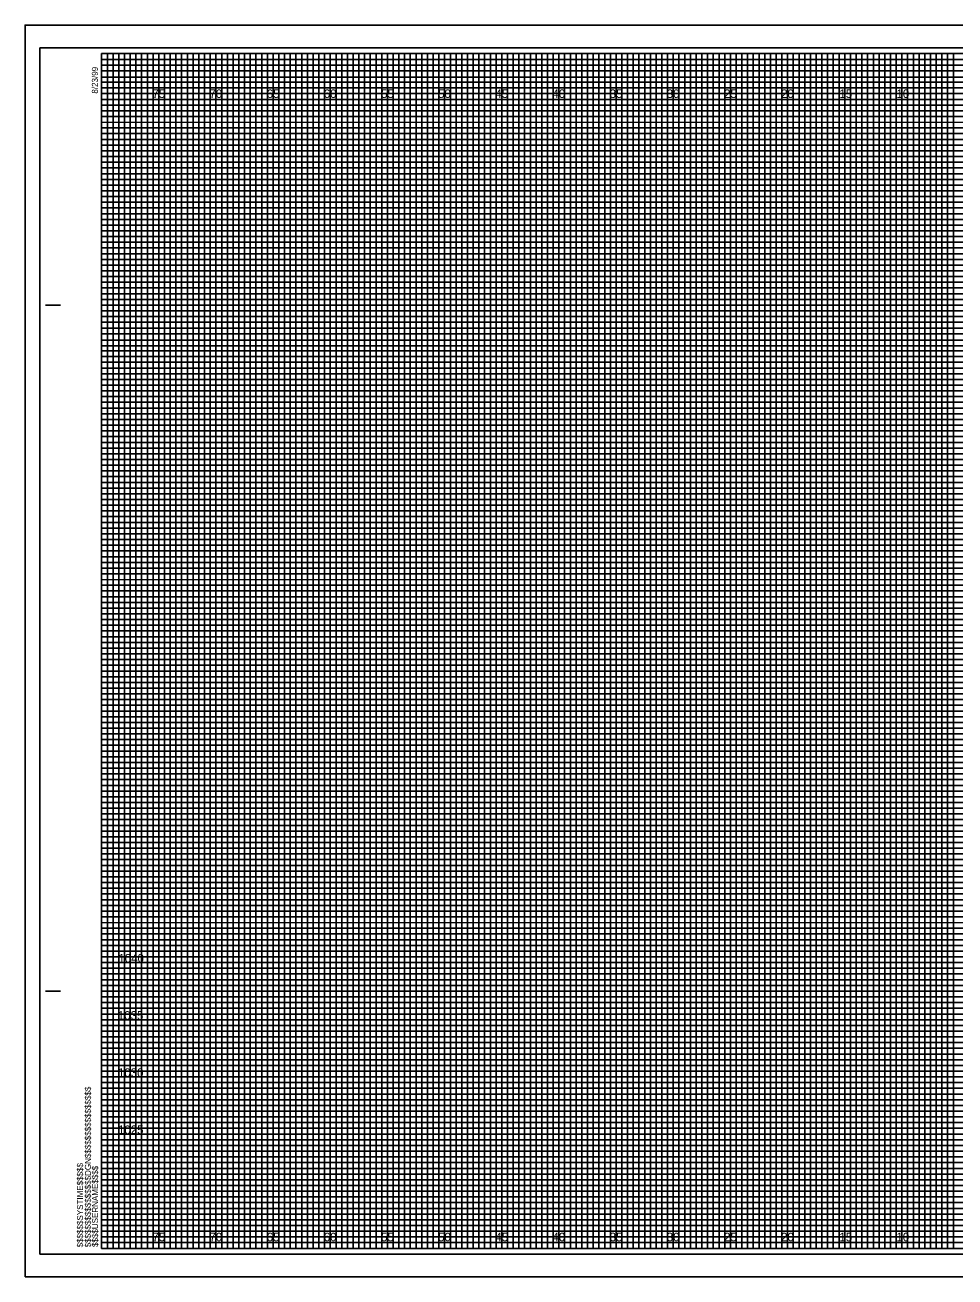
# Model space of a CAD drawing. Extents: x -7 to 162, y -2 to 987.
# Drawn here: x -6.7 to 74.6, y 877.5 to 987 of the extents above; entities that cross this region are included whole.
import ezdxf

# ---------------------------------------------------------------- set-up
doc = ezdxf.new("R2010")
doc.units = 0
for name, color, linetype in [('Exist Cross Section Cell', 7, 'Continuous'), ('Exist XS Center Line Elevation Label', 7, 'Continuous'), ('Exist XS Ground Line', 7, 'Continuous'), ('Prop CMT Concrete Structures', 7, 'Continuous'), ('Prop CMT Guardrail Widen Shoulder', 7, 'Continuous'), ('Prop CMT Pvmt Course 1', 7, 'Continuous'), ('Prop CMT Pvmt Surface', 7, 'Continuous'), ('Prop CMT Shld Paved Course 1', 7, 'Continuous'), ('Prop CMT Slope Grass', 7, 'Continuous'), ('Prop CMT Subgrade Earthwork', 7, 'Continuous'), ('Typical Text Label CELL', 7, 'Continuous')]:
    doc.layers.add(name, color=color, linetype=linetype)

msp = doc.modelspace()

# ---------------------------------------------------------------- linework, layer by layer
at = {"layer": 'Exist XS Center Line Elevation Label'}
for points in [[(0, 984.5), (2.5, 984.5), (2.5, 880), (7.5, 880), (7.5, 984.5), (12.5, 984.5), (12.5, 880), (17.5, 880), (17.5, 984.5), (22.5, 984.5), (22.5, 880), (27.5, 880), (27.5, 984.5), (32.5, 984.5), (32.5, 880), (37.5, 880), (37.5, 984.5), (42.5, 984.5), (42.5, 880), (47.5, 880), (47.5, 984.5), (52.5, 984.5), (52.5, 880), (57.5, 880), (57.5, 984.5), (62.5, 984.5), (62.5, 880), (67.5, 880), (67.5, 984.5), (72.5, 984.5), (72.5, 880), (77.5, 880)], [(0, 982), (137.5, 982)], [(0, 972.5), (160, 972.5), (160, 977.5), (0, 977.5)], [(0, 962.5), (160, 962.5), (160, 967.5), (0, 967.5)], [(0, 952.5), (160, 952.5), (160, 957.5), (0, 957.5)], [(0, 942.5), (160, 942.5), (160, 947.5), (0, 947.5)], [(0, 932.5), (160, 932.5), (160, 937.5), (0, 937.5)], [(0, 922.5), (160, 922.5), (160, 927.5), (0, 927.5)], [(0, 912.5), (160, 912.5), (160, 917.5), (0, 917.5)], [(0, 902.5), (160, 902.5), (160, 907.5), (0, 907.5)], [(0, 892.5), (160, 892.5), (160, 897.5), (0, 897.5)], [(0, 882.5), (160, 882.5), (160, 887.5), (0, 887.5)]]:
    msp.add_lwpolyline(points, dxfattribs=at)
at = {"layer": 'Exist XS Ground Line'}
for p, q in [((5, 984.5), (0, 984.5)), ((5, 880), (5, 984.5)), ((15, 984.5), (10, 984.5)), ((10, 984.5), (10, 880)), ((15, 880), (15, 984.5)), ((25, 984.5), (20, 984.5)), ((20, 984.5), (20, 880)), ((25, 880), (25, 984.5)), ((35, 984.5), (30, 984.5)), ((30, 984.5), (30, 880)), ((35, 880), (35, 984.5)), ((45, 984.5), (40, 984.5)), ((40, 984.5), (40, 880)), ((45, 880), (45, 984.5)), ((55, 984.5), (50, 984.5)), ((50, 984.5), (50, 880)), ((55, 880), (55, 984.5)), ((65, 984.5), (60, 984.5)), ((60, 984.5), (60, 880)), ((65, 880), (65, 984.5)), ((75, 984.5), (70, 984.5)), ((70, 984.5), (70, 880)), ((10, 880), (5, 880)), ((20, 880), (15, 880)), ((30, 880), (25, 880)), ((40, 880), (35, 880)), ((50, 880), (45, 880)), ((60, 880), (55, 880)), ((70, 880), (65, 880))]:
    msp.add_line(p, q, dxfattribs=at)
for points in [[(0, 980), (160, 980), (160, 975), (0, 975)], [(0, 970), (160, 970), (160, 965), (0, 965)], [(0, 960), (160, 960), (160, 955), (0, 955)], [(0, 950), (160, 950), (160, 945), (0, 945)], [(0, 940), (160, 940), (160, 935), (0, 935)], [(0, 930), (160, 930), (160, 925), (0, 925)], [(0, 920), (160, 920), (160, 915), (0, 915)], [(0, 910), (160, 910), (160, 905), (0, 905)], [(0, 900), (160, 900), (160, 895), (0, 895)], [(0, 890), (160, 890), (160, 885), (0, 885)]]:
    msp.add_lwpolyline(points, dxfattribs=at)
at = {"layer": 'Prop CMT Concrete Structures'}
for p, q in [((5, 880), (5, 984.5)), ((10, 880), (10, 984.5)), ((15, 880), (15, 984.5)), ((20, 880), (20, 984.5)), ((25, 880), (25, 984.5)), ((30, 880), (30, 984.5)), ((35, 880), (35, 984.5)), ((40, 880), (40, 984.5)), ((45, 880), (45, 984.5)), ((50, 880), (50, 984.5)), ((55, 880), (55, 984.5)), ((60, 880), (60, 984.5)), ((65, 880), (65, 984.5)), ((70, 880), (70, 984.5)), ((0, 980), (160, 980)), ((0, 975), (160, 975)), ((0, 970), (160, 970)), ((0, 965), (160, 965)), ((0, 960), (160, 960)), ((0, 955), (160, 955)), ((0, 950), (160, 950)), ((0, 945), (160, 945)), ((0, 940), (160, 940)), ((0, 935), (160, 935)), ((0, 930), (160, 930)), ((0, 925), (160, 925)), ((0, 920), (160, 920)), ((0, 915), (160, 915)), ((0, 910), (160, 910)), ((0, 905), (160, 905)), ((0, 900), (160, 900)), ((0, 895), (160, 895)), ((0, 890), (160, 890)), ((0, 885), (160, 885))]:
    msp.add_line(p, q, dxfattribs=at)
at = {"layer": 'Prop CMT Guardrail Widen Shoulder'}
for p, q in [((161.65, 987), (-6.7, 987)), ((-6.7, 987), (-6.7, 877.5)), ((-6.7, 877.5), (161.65, 877.5))]:
    msp.add_line(p, q, dxfattribs=at)
at = {"layer": 'Prop CMT Pvmt Course 1'}
msp.add_lwpolyline([(-6.7, 877.5), (161.65, 877.5), (161.65, 987), (-6.7, 987)], close=True, dxfattribs=at)
at = {"layer": 'Prop CMT Pvmt Surface'}
for points in [[(0, 880), (0.5, 880), (0.5, 984.5), (1, 984.5), (1, 880)], [(1, 880), (1.5, 880), (1.5, 984.5), (2, 984.5), (2, 880)], [(2.5, 880), (3, 880), (3, 984.5), (3.5, 984.5), (3.5, 880)], [(3.5, 880), (4, 880), (4, 984.5), (4.5, 984.5), (4.5, 880)], [(5, 880), (5.5, 880), (5.5, 984.5), (6, 984.5), (6, 880)], [(6, 880), (6.5, 880), (6.5, 984.5), (7, 984.5), (7, 880)], [(7.5, 880), (8, 880), (8, 984.5), (8.5, 984.5), (8.5, 880)], [(8.5, 880), (9, 880), (9, 984.5), (9.5, 984.5), (9.5, 880)], [(10, 880), (10.5, 880), (10.5, 984.5), (11, 984.5), (11, 880)], [(11, 880), (11.5, 880), (11.5, 984.5), (12, 984.5), (12, 880)], [(12.5, 880), (13, 880), (13, 984.5), (13.5, 984.5), (13.5, 880)], [(13.5, 880), (14, 880), (14, 984.5), (14.5, 984.5), (14.5, 880)], [(15, 880), (15.5, 880), (15.5, 984.5), (16, 984.5), (16, 880)], [(16, 880), (16.5, 880), (16.5, 984.5), (17, 984.5), (17, 880)], [(17.5, 880), (18, 880), (18, 984.5), (18.5, 984.5), (18.5, 880)], [(18.5, 880), (19, 880), (19, 984.5), (19.5, 984.5), (19.5, 880)], [(20, 880), (20.5, 880), (20.5, 984.5), (21, 984.5), (21, 880)], [(21, 880), (21.5, 880), (21.5, 984.5), (22, 984.5), (22, 880)], [(22.5, 880), (23, 880), (23, 984.5), (23.5, 984.5), (23.5, 880)], [(23.5, 880), (24, 880), (24, 984.5), (24.5, 984.5), (24.5, 880)], [(25, 880), (25.5, 880), (25.5, 984.5), (26, 984.5), (26, 880)], [(26, 880), (26.5, 880), (26.5, 984.5), (27, 984.5), (27, 880)], [(27.5, 880), (28, 880), (28, 984.5), (28.5, 984.5), (28.5, 880)], [(28.5, 880), (29, 880), (29, 984.5), (29.5, 984.5), (29.5, 880)], [(30, 880), (30.5, 880), (30.5, 984.5), (31, 984.5), (31, 880)], [(31, 880), (31.5, 880), (31.5, 984.5), (32, 984.5), (32, 880)], [(32.5, 880), (33, 880), (33, 984.5), (33.5, 984.5), (33.5, 880)], [(33.5, 880), (34, 880), (34, 984.5), (34.5, 984.5), (34.5, 880)], [(35, 880), (35.5, 880), (35.5, 984.5), (36, 984.5), (36, 880)], [(36, 880), (36.5, 880), (36.5, 984.5), (37, 984.5), (37, 880)], [(37.5, 880), (38, 880), (38, 984.5), (38.5, 984.5), (38.5, 880)], [(38.5, 880), (39, 880), (39, 984.5), (39.5, 984.5), (39.5, 880)], [(40, 880), (40.5, 880), (40.5, 984.5), (41, 984.5), (41, 880)], [(41, 880), (41.5, 880), (41.5, 984.5), (42, 984.5), (42, 880)], [(42.5, 880), (43, 880), (43, 984.5), (43.5, 984.5), (43.5, 880)], [(43.5, 880), (44, 880), (44, 984.5), (44.5, 984.5), (44.5, 880)], [(45, 880), (45.5, 880), (45.5, 984.5), (46, 984.5), (46, 880)], [(46, 880), (46.5, 880), (46.5, 984.5), (47, 984.5), (47, 880)], [(47.5, 880), (48, 880), (48, 984.5), (48.5, 984.5), (48.5, 880)], [(48.5, 880), (49, 880), (49, 984.5), (49.5, 984.5), (49.5, 880)], [(50, 880), (50.5, 880), (50.5, 984.5), (51, 984.5), (51, 880)], [(51, 880), (51.5, 880), (51.5, 984.5), (52, 984.5), (52, 880)], [(52.5, 880), (53, 880), (53, 984.5), (53.5, 984.5), (53.5, 880)], [(53.5, 880), (54, 880), (54, 984.5), (54.5, 984.5), (54.5, 880)], [(55, 880), (55.5, 880), (55.5, 984.5), (56, 984.5), (56, 880)], [(56, 880), (56.5, 880), (56.5, 984.5), (57, 984.5), (57, 880)], [(57.5, 880), (58, 880), (58, 984.5), (58.5, 984.5), (58.5, 880)], [(58.5, 880), (59, 880), (59, 984.5), (59.5, 984.5), (59.5, 880)], [(60, 880), (60.5, 880), (60.5, 984.5), (61, 984.5), (61, 880)], [(61, 880), (61.5, 880), (61.5, 984.5), (62, 984.5), (62, 880)], [(62.5, 880), (63, 880), (63, 984.5), (63.5, 984.5), (63.5, 880)], [(63.5, 880), (64, 880), (64, 984.5), (64.5, 984.5), (64.5, 880)], [(65, 880), (65.5, 880), (65.5, 984.5), (66, 984.5), (66, 880)], [(66, 880), (66.5, 880), (66.5, 984.5), (67, 984.5), (67, 880)], [(67.5, 880), (68, 880), (68, 984.5), (68.5, 984.5), (68.5, 880)], [(68.5, 880), (69, 880), (69, 984.5), (69.5, 984.5), (69.5, 880)], [(70, 880), (70.5, 880), (70.5, 984.5), (71, 984.5), (71, 880)], [(71, 880), (71.5, 880), (71.5, 984.5), (72, 984.5), (72, 880)], [(72.5, 880), (73, 880), (73, 984.5), (73.5, 984.5), (73.5, 880)], [(73.5, 880), (74, 880), (74, 984.5), (74.5, 984.5), (74.5, 880)]]:
    msp.add_lwpolyline(points, dxfattribs=at)
at = {"layer": 'Prop CMT Shld Paved Course 1'}
for p, q in [((0, 984), (130, 984)), ((130, 983.49), (0, 983.49)), ((0, 983.49), (0, 983)), ((0, 983), (130, 983)), ((130, 982.45), (0, 982.45)), ((0, 982.45), (0, 981.5)), ((0, 981.5), (160, 981.5))]:
    msp.add_line(p, q, dxfattribs=at)
for points in [[(0, 981), (135, 981), (160, 981), (160, 981), (0, 981)], [(0, 980.5), (160, 980.5), (160, 979.5), (0, 979.5)], [(0, 979), (160, 979), (160, 978.5), (0, 978.49)], [(0, 978), (160, 978), (160, 977), (0, 977)], [(0, 976.5), (160, 976.5), (160, 976), (0, 976)], [(0, 975.5), (160, 975.5), (160, 974.5), (0, 974.5)], [(0, 974), (160, 974), (160, 973.5), (0, 973.5)], [(0, 973), (160, 973), (160, 972), (0, 972)], [(0, 971.5), (160, 971.5), (160, 971), (0, 971)], [(0, 970.5), (160, 970.5), (160, 969.5), (0, 969.5)], [(0, 969), (160, 969), (160, 968.5), (0, 968.5)], [(0, 968), (160, 968), (160, 966.98), (160, 966.5), (160, 966), (0, 966)], [(0, 967), (160, 967), (160, 966.5), (0, 966.5)], [(0, 965.5), (160, 965.5), (160, 964.5), (0, 964.51)], [(0, 964.51), (160, 964.5), (160, 964), (0, 964)], [(0, 963.5), (160, 963.5), (160, 963), (0, 963)], [(0, 962), (160, 962), (160, 961.5), (0, 961.5)], [(0, 961), (160, 961), (160, 960.5), (0, 960.5)], [(-0.04, 959.45), (160, 959.45), (160, 958.94), (-0.04, 958.94)], [(0, 958.5), (160, 958.5), (160, 958), (0, 958)], [(0, 957), (160, 957), (160, 956.5), (0, 956.5)], [(0, 956), (160, 956), (160, 955.5), (0, 955.5)], [(0, 954.5), (160, 954.5), (160, 954), (0, 954)], [(0, 953.5), (160, 953.5), (160, 953), (0, 953)], [(0, 952), (160, 952), (160, 951.5), (0, 951.5)], [(0, 951), (160, 951), (160, 950.5), (0, 950.5)], [(0, 949.5), (160, 949.5), (160, 948.99), (0, 949)], [(0, 948.5), (160, 948.5), (160, 948), (0, 948)], [(0, 947), (160, 947), (160, 946.5), (0, 946.5)], [(0, 946), (160, 946), (160, 945.5), (0, 945.5)], [(0, 944.5), (160, 944.5), (160, 944), (0, 944)], [(0, 943.5), (160, 943.5), (160, 943), (0, 943)], [(0, 942), (160, 942), (160, 941.5), (0, 941.5)], [(0, 941), (160, 941), (160, 940.5), (0, 940.5)], [(0, 939.5), (160, 939.5), (160, 939), (0, 939)], [(0, 938.5), (160.03, 938.46), (160, 938), (0, 938)], [(0, 937), (160, 937), (160, 936.5), (0, 936.5)], [(0, 936), (160, 936), (160, 935.5), (0, 935.5)], [(0, 934.5), (160, 934.5), (160, 934), (0, 934)], [(0, 933.5), (160, 933.5), (160, 933), (0, 933)], [(0, 932), (160, 932), (160, 931.5), (0, 931.5)], [(0, 931), (160, 931), (160, 930.5), (0, 930.5)], [(0, 929.5), (160, 929.5), (160, 929), (0, 929)], [(0, 928.5), (160, 928.5), (160, 928), (0, 928)], [(0, 927), (160, 927), (160, 926.5), (0, 926.5)], [(0, 926), (160, 926), (160, 925.5), (0, 925.5)], [(0, 924.5), (160, 924.5), (160, 924), (0, 924)], [(0, 923.5), (160, 923.5), (160, 923), (0, 923)], [(0, 922), (160, 922), (160, 921.5), (0, 921.5)], [(0, 921), (160, 921), (160, 920.5), (0, 920.5)], [(0, 919.5), (160, 919.5), (160, 918.99), (0, 919)], [(0, 918.5), (160, 918.5), (160, 918), (0, 918)], [(0, 917), (160, 917), (160, 916.5), (0, 916.5)], [(0, 916), (160, 916), (160, 915.5), (0, 915.5)], [(0, 914.5), (160, 914.5), (160, 914), (0, 914)], [(0, 913.5), (160, 913.5), (160, 913), (0, 913)], [(0, 912), (160, 912), (160, 911.5), (0, 911.5)], [(0, 911), (160, 911), (160, 910.5), (0, 910.5)], [(0, 909.5), (160, 909.5), (160, 909), (0, 909)], [(0, 908.5), (160.03, 908.46), (160, 908), (0, 908)], [(0, 907), (160, 907), (160, 906.5), (0, 906.5)], [(0, 906), (160, 906), (160, 905.5), (0, 905.5)], [(0, 904.5), (160, 904.5), (160, 904), (0, 904)], [(0, 903.5), (160, 903.5), (160, 903), (0, 903)], [(0, 902), (160, 902), (160, 901.5), (0, 901.5)], [(0, 901), (160, 901), (160, 900.5), (0, 900.5)], [(0, 899.5), (160, 899.5), (160, 899), (0, 899)], [(0, 898.5), (160, 898.5), (160, 898), (0, 898)], [(0, 897), (160, 897), (160, 896.5), (0, 896.5)], [(0, 896), (160, 896), (160, 895.5), (0, 895.5)], [(0, 894.5), (160, 894.5), (160, 894), (0, 894)], [(0, 893.5), (160, 893.5), (160, 893), (0, 893)], [(0, 892), (160, 892), (160, 891.5), (0, 891.5)], [(0, 891), (160, 891), (160, 890.5), (0, 890.5)], [(0, 889.5), (160, 889.5), (160, 889), (0, 889)], [(0, 888.5), (160, 888.5), (160, 888), (0, 888)], [(0, 887), (160, 887), (160, 886.5), (0, 886.5)], [(0, 886), (160, 886), (160, 885.5), (0, 885.5)], [(0, 884.5), (160, 884.5), (160, 884), (0, 884)], [(0, 883.5), (160, 883.5), (160, 883), (0, 883)], [(0, 882), (160, 882), (160, 881.5), (0, 881.5)], [(0, 881), (160, 881), (160, 880.5), (0, 880.5)]]:
    msp.add_lwpolyline(points, dxfattribs=at)
at = {"layer": 'Prop CMT Slope Grass'}
msp.add_lwpolyline([(-5.4, 879.5), (161.2, 879.5), (161.2, 985), (-5.4, 985)], close=True, dxfattribs=at)
at = {"layer": 'Prop CMT Subgrade Earthwork'}
for p, q in [((-4.9, 962.5), (-3.65, 962.5)), ((-4.85, 962.5), (-3.6, 962.5)), ((-4.9, 902.5), (-3.65, 902.5)), ((-4.85, 902.5), (-3.6, 902.5)), ((0, 880), (0, 880)), ((0, 880), (0, 880)), ((0, 880), (0, 880)), ((0, 880), (0, 880)), ((0, 880), (0, 880)), ((0, 880), (0, 880)), ((0, 880), (0, 880))]:
    msp.add_line(p, q, dxfattribs=at)
msp.add_lwpolyline([(160, 984.5), (0, 984.5), (0, 880), (160, 880)], close=True, dxfattribs=at)

# ---------------------------------------------------------------- texts
at = {"layer": 'Exist Cross Section Cell'}
for s, p in [('75', (4.44, 980.62)), ('70', (9.43, 980.62)), ('65', (14.44, 980.62)), ('60', (19.43, 980.62)), ('55', (24.44, 980.62)), ('50', (29.43, 980.62)), ('45', (34.44, 980.62)), ('40', (39.43, 980.62)), ('35', (44.44, 980.62)), ('30', (49.43, 980.62)), ('25', (54.44, 980.62)), ('20', (59.43, 980.62)), ('15', (64.53, 980.62)), ('10', (69.52, 980.62)), ('75', (4.44, 880.62)), ('70', (9.43, 880.62)), ('65', (14.44, 880.62)), ('60', (19.43, 880.62)), ('55', (24.44, 880.62)), ('50', (29.43, 880.62)), ('45', (34.44, 880.62)), ('40', (39.43, 880.62)), ('35', (44.44, 880.62)), ('30', (49.43, 880.62)), ('25', (54.44, 880.62)), ('20', (59.43, 880.62)), ('15', (64.53, 880.62)), ('10', (69.52, 880.62))]:
    msp.add_text(s, height=0.75, dxfattribs=at).set_placement(p)
at = {"layer": 'Prop CMT Subgrade Earthwork'}
for s, p in [('8/23/99', (-0.33, 981)), ('$$$$$$$$$$$$$$$$DGN$$$$$$$$$$$$$$$$', (-0.94, 880.09)), ('$$$$$$SYSTIME$$$$$', (-1.63, 880.09)), ('$$$$USERNAME$$$$', (-0.31, 880.12))]:
    msp.add_text(s, height=0.525, rotation=90, dxfattribs=at).set_placement(p)
at = {"layer": 'Typical Text Label CELL'}
for s, p in [('1040', (1.47, 905)), ('1035', (1.42, 900)), ('1030', (1.43, 895)), ('1025', (1.43, 890))]:
    msp.add_text(s, height=0.75, dxfattribs=at).set_placement(p)

doc.saveas('drawing.dxf')
